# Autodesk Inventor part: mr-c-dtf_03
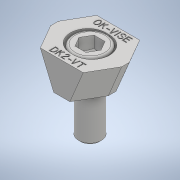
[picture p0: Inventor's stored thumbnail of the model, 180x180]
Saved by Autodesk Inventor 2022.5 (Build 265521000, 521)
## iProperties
Part Number: mr-c-dtf_03
Material: 一般
Document SubType Name: Modeling
Designer: ImaoCorp
Density: 1 g/cm^3
Appearance: 既定
Author: ImaoCorp
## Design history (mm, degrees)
feature "mr-c-dtf_03"
node "ソリッド1"
